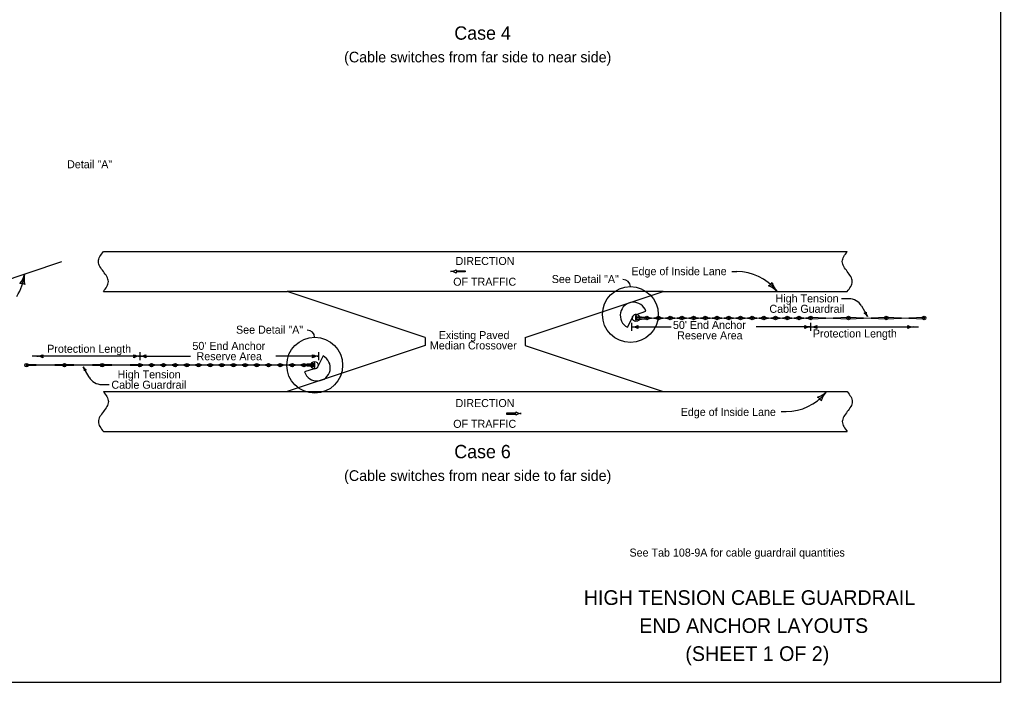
# Model space of a CAD drawing. Extents: x 10133 to 81668, y 7924 to 11018.
# Drawn here: x 11797 to 13268, y 7924 to 8918 of the extents above; entities that cross this region are included whole.
import ezdxf

# ---------------------------------------------------------------- set-up
doc = ezdxf.new("R2010")
doc.units = 0
for name, color, linetype in [('dsnCellElements', 7, 'Continuous'), ('dsnShadingGranular', 7, 'Continuous'), ('DsnShtRevisedText', 7, 'Continuous'), ('dsnStdDimension', 7, 'Continuous'), ('Level 8', 7, 'Continuous'), ('SheetBorder', 7, 'Continuous')]:
    doc.layers.add(name, color=color, linetype=linetype)

msp = doc.modelspace()

# ---------------------------------------------------------------- linework, layer by layer
at = {"layer": 'dsnCellElements'}
for p, q in [((12721, 8472.6), (12737.8, 8471.4)), ((12721, 8471.4), (12736.9, 8471.4)), ((12721, 8469.2), (12736.9, 8469.2)), ((12721, 8468), (12737.8, 8469.2)), ((12737.8, 8469.2), (12754.4, 8471.4)), ((12737.8, 8471.4), (12754.4, 8469.2)), ((12755.3, 8469.2), (12771.9, 8471.4)), ((12755.3, 8471.4), (12771.9, 8469.2)), ((12772.9, 8469.2), (12789.5, 8471.4)), ((12772.9, 8471.4), (12789.5, 8469.2)), ((12790.4, 8469.2), (12807, 8471.4)), ((12790.4, 8471.4), (12807, 8469.2)), ((12808, 8469.2), (12824.6, 8471.4)), ((12808, 8471.4), (12824.6, 8469.2)), ((12825.5, 8469.2), (12842.1, 8471.4)), ((12825.5, 8471.4), (12842.1, 8469.2)), ((12843.1, 8471.4), (12859.7, 8469.2)), ((12843.1, 8469.2), (12859.7, 8471.4)), ((12860.6, 8469.2), (12877.2, 8471.4)), ((12860.6, 8471.4), (12877.2, 8469.2)), ((12878.2, 8469.2), (12894.8, 8471.4)), ((12878.2, 8471.4), (12894.8, 8469.2)), ((12895.7, 8469.2), (12912.3, 8471.4)), ((12895.7, 8471.4), (12912.3, 8469.2)), ((12913.3, 8469.2), (12929.8, 8471.4)), ((12913.3, 8471.4), (12929.8, 8469.2)), ((12930.8, 8469.2), (12947.4, 8471.4)), ((12930.8, 8471.4), (12947.4, 8469.2)), ((12948.4, 8469.2), (12964.9, 8471.4)), ((12948.4, 8471.4), (12964.9, 8469.2)), ((12965.9, 8469.2), (12982.5, 8471.4)), ((12965.9, 8471.4), (12982.5, 8469.2)), ((12983.4, 8469.2), (13039.2, 8471.4)), ((12983.4, 8471.4), (13039.2, 8469.2)), ((13040.1, 8469.2), (13095.9, 8471.4)), ((13040.1, 8471.4), (13095.9, 8469.2)), ((13096.9, 8469.2), (13152.6, 8471.4)), ((13096.9, 8471.4), (13152.6, 8469.2)), ((11863.2, 8400.6), (11807.4, 8398.3)), ((11863.2, 8398.3), (11807.4, 8400.6)), ((11919.9, 8400.6), (11864.1, 8398.3)), ((11919.9, 8398.3), (11864.1, 8400.6)), ((11976.6, 8400.6), (11920.8, 8398.3)), ((11976.6, 8398.3), (11920.8, 8400.6)), ((11994.2, 8400.6), (11977.5, 8398.3)), ((11994.2, 8398.3), (11977.5, 8400.6)), ((12011.7, 8400.6), (11995.1, 8398.3)), ((12011.7, 8398.3), (11995.1, 8400.6)), ((12029.3, 8400.6), (12012.6, 8398.3)), ((12029.3, 8398.3), (12012.6, 8400.6)), ((12046.8, 8400.6), (12030.2, 8398.3)), ((12046.8, 8398.3), (12030.2, 8400.6)), ((12064.4, 8400.6), (12047.7, 8398.3)), ((12064.4, 8398.3), (12047.7, 8400.6)), ((12081.9, 8400.6), (12065.3, 8398.3)), ((12081.9, 8398.3), (12065.3, 8400.6)), ((12099.4, 8400.6), (12082.8, 8398.3)), ((12099.4, 8398.3), (12082.8, 8400.6)), ((12117, 8398.3), (12100.4, 8400.6)), ((12117, 8400.6), (12100.4, 8398.3)), ((12134.5, 8400.6), (12117.9, 8398.3)), ((12134.5, 8398.3), (12117.9, 8400.6)), ((12152.1, 8400.6), (12135.5, 8398.3)), ((12152.1, 8398.3), (12135.5, 8400.6)), ((12169.6, 8400.6), (12153, 8398.3)), ((12169.6, 8398.3), (12153, 8400.6)), ((12187.2, 8400.6), (12170.6, 8398.3)), ((12187.2, 8398.3), (12170.6, 8400.6)), ((12204.7, 8400.6), (12188.1, 8398.3)), ((12204.7, 8398.3), (12188.1, 8400.6)), ((12222.3, 8400.6), (12205.7, 8398.3)), ((12222.3, 8398.3), (12205.7, 8400.6)), ((12239, 8401.8), (12222.3, 8400.6)), ((12239, 8400.6), (12223.2, 8400.6)), ((12239, 8397.2), (12222.3, 8398.3)), ((12239, 8398.3), (12223.2, 8398.3))]:
    msp.add_line(p, q, dxfattribs=at)
for points in [[(12720.4, 8473.3), (12720.4, 8467.3), (12721.6, 8467.3), (12721.6, 8473.3)], [(12736.9, 8471.4), (12736.9, 8469.2), (12737.8, 8469.2), (12737.8, 8471.4)], [(12754.4, 8471.4), (12754.4, 8469.2), (12755.3, 8469.2), (12755.3, 8471.4)], [(12772, 8471.4), (12772, 8469.2), (12772.9, 8469.2), (12772.9, 8471.4)], [(12789.5, 8471.4), (12789.5, 8469.2), (12790.4, 8469.2), (12790.4, 8471.4)], [(12807.1, 8471.4), (12807.1, 8469.2), (12808, 8469.2), (12808, 8471.4)], [(12824.6, 8471.4), (12824.6, 8469.2), (12825.5, 8469.2), (12825.5, 8471.4)], [(12842.1, 8471.4), (12842.1, 8469.2), (12843.1, 8469.2), (12843.1, 8471.4)], [(12859.7, 8471.4), (12859.7, 8469.2), (12860.6, 8469.2), (12860.6, 8471.4)], [(12877.2, 8471.4), (12877.2, 8469.2), (12878.2, 8469.2), (12878.2, 8471.4)], [(12894.8, 8471.4), (12894.8, 8469.2), (12895.7, 8469.2), (12895.7, 8471.4)], [(12912.3, 8471.4), (12912.3, 8469.2), (12913.3, 8469.2), (12913.3, 8471.4)], [(12929.8, 8471.4), (12929.8, 8469.2), (12930.8, 8469.2), (12930.8, 8471.4)], [(12947.4, 8471.4), (12947.4, 8469.2), (12948.4, 8469.2), (12948.4, 8471.4)], [(12964.9, 8471.4), (12964.9, 8469.2), (12965.9, 8469.2), (12965.9, 8471.4)], [(12982.5, 8471.4), (12982.5, 8469.2), (12983.4, 8469.2), (12983.4, 8471.4)], [(12982.5, 8471.4), (12982.5, 8469.2), (12983.4, 8469.2), (12983.4, 8471.4)], [(13039.2, 8471.4), (13039.2, 8469.2), (13040.1, 8469.2), (13040.1, 8471.4)], [(13039.2, 8471.4), (13039.2, 8469.2), (13040.1, 8469.2), (13040.1, 8471.4)], [(13095.9, 8471.4), (13095.9, 8469.2), (13096.9, 8469.2), (13096.9, 8471.4)], [(13095.9, 8471.4), (13095.9, 8469.2), (13096.9, 8469.2), (13096.9, 8471.4)], [(13152.6, 8471.4), (13152.6, 8469.2), (13153.6, 8469.2), (13153.6, 8471.4)], [(11807.4, 8398.3), (11807.4, 8400.6), (11806.5, 8400.6), (11806.5, 8398.3)], [(11864.1, 8398.3), (11864.1, 8400.6), (11863.2, 8400.6), (11863.2, 8398.3)], [(11864.1, 8398.3), (11864.1, 8400.6), (11863.2, 8400.6), (11863.2, 8398.3)], [(11920.8, 8398.3), (11920.8, 8400.6), (11919.9, 8400.6), (11919.9, 8398.3)], [(11920.8, 8398.3), (11920.8, 8400.6), (11919.9, 8400.6), (11919.9, 8398.3)], [(11977.5, 8398.3), (11977.5, 8400.6), (11976.6, 8400.6), (11976.6, 8398.3)], [(11977.5, 8398.3), (11977.5, 8400.6), (11976.6, 8400.6), (11976.6, 8398.3)], [(11995.1, 8398.3), (11995.1, 8400.6), (11994.2, 8400.6), (11994.2, 8398.3)], [(12012.6, 8398.3), (12012.6, 8400.6), (12011.7, 8400.6), (12011.7, 8398.3)], [(12030.2, 8398.3), (12030.2, 8400.6), (12029.3, 8400.6), (12029.3, 8398.3)], [(12047.7, 8398.3), (12047.7, 8400.6), (12046.8, 8400.6), (12046.8, 8398.3)], [(12065.3, 8398.3), (12065.3, 8400.6), (12064.4, 8400.6), (12064.4, 8398.3)], [(12082.8, 8398.3), (12082.8, 8400.6), (12081.9, 8400.6), (12081.9, 8398.3)], [(12100.4, 8398.3), (12100.4, 8400.6), (12099.4, 8400.6), (12099.4, 8398.3)], [(12117.9, 8398.3), (12117.9, 8400.6), (12117, 8400.6), (12117, 8398.3)], [(12135.5, 8398.3), (12135.5, 8400.6), (12134.5, 8400.6), (12134.5, 8398.3)], [(12153, 8398.3), (12153, 8400.6), (12152.1, 8400.6), (12152.1, 8398.3)], [(12170.6, 8398.3), (12170.6, 8400.6), (12169.6, 8400.6), (12169.6, 8398.3)], [(12188.1, 8398.3), (12188.1, 8400.6), (12187.2, 8400.6), (12187.2, 8398.3)], [(12205.7, 8398.3), (12205.7, 8400.6), (12204.7, 8400.6), (12204.7, 8398.3)], [(12223.2, 8398.3), (12223.2, 8400.6), (12222.3, 8400.6), (12222.3, 8398.3)], [(12239.6, 8396.5), (12239.6, 8402.5), (12238.4, 8402.5), (12238.4, 8396.5)]]:
    msp.add_lwpolyline(points, close=True, dxfattribs=at)
for centre, radius in [((12721, 8470.3), 5.4), ((12737.3, 8470.3), 2.66), ((12754.8, 8470.3), 2.66), ((12772.4, 8470.3), 2.66), ((12789.9, 8470.3), 2.66), ((12807.5, 8470.3), 2.66), ((12825, 8470.3), 2.66), ((12842.6, 8470.3), 2.66), ((12860.1, 8470.3), 2.66), ((12877.7, 8470.3), 2.66), ((12895.2, 8470.3), 2.66), ((12912.8, 8470.3), 2.66), ((12930.3, 8470.3), 2.66), ((12947.9, 8470.3), 2.66), ((12965.4, 8470.3), 2.66), ((12983, 8470.3), 2.66), ((12983, 8470.3), 2.66), ((13039.7, 8470.3), 2.66), ((13039.7, 8470.3), 2.66), ((13096.4, 8470.3), 2.66), ((13096.4, 8470.3), 2.66), ((13153.1, 8470.3), 2.66), ((11807, 8399.5), 2.66), ((11863.7, 8399.5), 2.66), ((11863.7, 8399.5), 2.66), ((11920.4, 8399.5), 2.66), ((11920.4, 8399.5), 2.66), ((11977.1, 8399.5), 2.66), ((11977.1, 8399.5), 2.66), ((11994.6, 8399.5), 2.66), ((12012.2, 8399.5), 2.66), ((12029.7, 8399.5), 2.66), ((12047.3, 8399.5), 2.66), ((12064.8, 8399.5), 2.66), ((12082.3, 8399.5), 2.66), ((12099.9, 8399.5), 2.66), ((12117.4, 8399.5), 2.66), ((12135, 8399.5), 2.66), ((12152.5, 8399.5), 2.66), ((12170.1, 8399.5), 2.66), ((12187.6, 8399.5), 2.66), ((12205.2, 8399.5), 2.66), ((12222.7, 8399.5), 2.66), ((12239, 8399.5), 5.4)]:
    msp.add_circle(centre, radius, dxfattribs=at)
at = {"layer": 'DsnShtRevisedText'}
for p, q in [((11602.1, 8468.7), (11860.1, 8554.7)), ((12443, 8540.1), (12443, 8540.1)), ((12451.1, 8542.6), (12451.1, 8540.8)), ((12451.1, 8540.8), (12465, 8540.8)), ((12465, 8539.3), (12451.1, 8539.3)), ((12451.1, 8539.3), (12451.1, 8537.5)), ((12465, 8540.8), (12465, 8539.3)), ((12864.7, 8539.7), (12872.2, 8539.7)), ((13040.3, 8499.1), (13029.1, 8499.1)), ((13059.1, 8488.3), (13068, 8472.7)), ((12721.8, 8475.7), (12736, 8480.4)), ((12721.8, 8475.7), (12736, 8480.4)), ((12708.4, 8456.5), (12715.7, 8471.1)), ((12708.4, 8456.5), (12715.7, 8471.1)), ((12715, 8450.8), (12715, 8462.8)), ((12983.1, 8450.8), (12983.1, 8462.8)), ((12715, 8456.8), (12773.9, 8456.8)), ((12983.1, 8456.8), (12901.2, 8456.8)), ((12983.1, 8456.8), (13092.6, 8456.8)), ((13092.6, 8456.8), (13144.9, 8456.8)), ((11977, 8419), (11977, 8407)), ((12245.1, 8419), (12245.1, 8407)), ((11942.5, 8413), (11815.2, 8413)), ((11977, 8413), (11942.5, 8413)), ((11977, 8413), (12052.7, 8413)), ((12245.1, 8413), (12181.1, 8413)), ((12251.7, 8413.3), (12244.4, 8398.7)), ((12251.7, 8413.3), (12244.4, 8398.7)), ((11900.9, 8381.5), (11892.1, 8397.1)), ((12238.3, 8394.1), (12224.1, 8389.4)), ((12238.3, 8394.1), (12224.1, 8389.4)), ((11919.7, 8370.6), (11931, 8370.6)), ((12540.9, 8327.8), (12526.9, 8327.8)), ((12526.9, 8327.8), (12526.9, 8326.3)), ((12526.9, 8326.3), (12540.9, 8326.3)), ((12540.9, 8329.6), (12540.9, 8327.8)), ((12540.9, 8326.3), (12540.9, 8324.5)), ((12549, 8327.1), (12549, 8327.1)), ((12938.6, 8330), (12946.1, 8330))]:
    msp.add_line(p, q, dxfattribs=at)
for centre in [(12712.6, 8475.4), (12239.2, 8399.5)]:
    msp.add_circle(centre, 41.9, dxfattribs=at)
for centre, radius, start, end in [((11724.4, 8544.9), 80.1, 328.1378, 353.6325), ((11772.5, 8543.3), 32.4, 318.907, 346.9794), ((11835.6, 8528.7), 32.4, 166.9794, 195.0519), ((12442.3, 8556.4), 16.4, 272.352, 302.382), ((12442.3, 8523.7), 16.4, 57.618, 87.648), ((12872.2, 8463.6), 76.2, 39.0106, 90), ((11797.9, 8509.6), 12.5, 59.2461, 94.7128), ((12701.8, 8517), 10.8, 1.4994, 91.4994), ((12914.2, 8529.7), 12.5, 295.2639, 330.7306), ((12909, 8487.8), 32.4, 42.9973, 71.0698), ((12956.4, 8532), 32.4, 194.9248, 222.9973), ((12717.2, 8474.1), 19.8, 18.4349, 243.4349), ((12717.2, 8474.1), 19.8, 18.4349, 243.4349), ((13040.3, 8477.3), 21.8, 30.2243, 90), ((12721.1, 8470.3), 5.4, 81.8699, 171.8699), ((12721.1, 8470.3), 5.4, 81.8699, 171.8699), ((13062.3, 8482.5), 5.25, 282.498, 317.9647), ((13056.2, 8465.8), 13.6, 30.2314, 58.3038), ((13079.8, 8479.5), 13.6, 182.1589, 210.2314), ((12715, 8475.9), 19.1, 270, 298.0725), ((12731, 8456.8), 7.39, 162.2666, 197.7334), ((12967, 8456.8), 7.39, 342.2666, 17.7333), ((12983.1, 8475.9), 19.1, 241.9275, 270), ((12983.1, 8475.9), 19.1, 270, 298.0725), ((12999.1, 8456.8), 7.39, 162.2666, 197.7334), ((13121.5, 8456.8), 7.39, 342.2667, 17.7334), ((13137.6, 8475.9), 19.1, 241.9275, 270), ((12228.3, 8441.1), 10.8, 1.4994, 91.4994), ((12715, 8437.7), 19.1, 61.9275, 90), ((12983.1, 8437.7), 19.1, 90, 118.0725), ((12983.1, 8437.7), 19.1, 61.9275, 90), ((13137.6, 8437.7), 19.1, 90, 118.0725), ((11822.5, 8432.1), 19.1, 270, 298.0725), ((11838.5, 8413), 7.39, 162.2666, 197.7334), ((11960.9, 8413), 7.39, 342.2666, 17.7333), ((11977, 8432.1), 19.1, 241.9275, 270), ((11977, 8432.1), 19.1, 270, 298.0725), ((11993, 8413), 7.39, 162.2666, 197.7334), ((12229, 8413), 7.39, 342.2667, 17.7334), ((12245.1, 8432.1), 19.1, 241.9275, 270), ((11822.5, 8393.9), 19.1, 61.9275, 90), ((11977, 8393.9), 19.1, 90, 118.0725), ((11977, 8393.9), 19.1, 61.9275, 90), ((12242.8, 8395.6), 19.8, 198.4349, 63.4349), ((12242.8, 8395.6), 19.8, 198.4349, 63.4349), ((12245.1, 8393.9), 19.1, 90, 118.0725), ((11880.3, 8390.3), 13.6, 2.1589, 30.2314), ((11903.8, 8404), 13.6, 210.2314, 238.3038), ((11897.8, 8387.3), 5.25, 102.498, 137.9647), ((12239, 8399.5), 5.4, 261.8699, 351.8699), ((12239, 8399.5), 5.4, 261.8699, 351.8699), ((11919.7, 8392.4), 21.8, 210.2243, 270), ((12946.1, 8406.2), 76.2, 270, 320.9894), ((12982.9, 8382), 32.4, 288.9302, 317.0027), ((13030.3, 8337.8), 32.4, 137.0027, 165.0752), ((12988.1, 8340), 12.5, 29.2694, 64.7361), ((12549.7, 8343.4), 16.4, 237.618, 267.648), ((12549.7, 8310.7), 16.4, 92.352, 122.382)]:
    msp.add_arc(centre, radius, start, end, dxfattribs=at)
at = {"layer": 'dsnStdDimension'}
for p, q in [((11922.2, 8569.9), (13037.9, 8569.9)), ((11922.2, 8509.9), (12198, 8509.9)), ((12405, 8440.9), (12198, 8509.9)), ((12762, 8509.9), (12198, 8509.9)), ((12555, 8440.9), (12762, 8509.9)), ((12758.9, 8509.9), (13037.9, 8509.9)), ((12405, 8428.9), (12198, 8359.9)), ((12405, 8440.9), (12405, 8428.9)), ((12555, 8440.9), (12555, 8428.9)), ((12555, 8428.9), (12762, 8359.9)), ((11922.2, 8359.9), (12201.1, 8359.9)), ((12201.1, 8359.9), (12762, 8359.9)), ((12762, 8359.9), (13037.9, 8359.9)), ((11922.2, 8299.9), (13037.9, 8299.9))]:
    msp.add_line(p, q, dxfattribs=at)
for points in [[(11922.2, 8509.9), (11929.7, 8524.9), (11922.2, 8539.9), (11914.7, 8554.9), (11922.2, 8569.9)], [(13037.9, 8509.9), (13045.4, 8524.9), (13037.9, 8539.9), (13030.4, 8554.9), (13037.9, 8569.9)], [(11922.2, 8359.9), (11929.7, 8344.9), (11922.2, 8329.9), (11914.7, 8314.9), (11922.2, 8299.9)], [(13037.9, 8359.9), (13045.4, 8344.9), (13037.9, 8329.9), (13030.4, 8314.9), (13037.9, 8299.9)]]:
    msp.add_spline(points, degree=3, dxfattribs=at)
at = {"layer": 'SheetBorder'}
msp.add_lwpolyline([(10132.5, 9944), (13267.5, 9944), (13267.5, 7924), (10132.5, 7924)], close=True, dxfattribs=at)

# ---------------------------------------------------------------- texts
at = {"layer": 'dsnShadingGranular'}
for s, p in [('HIGH TENSION CABLE GUARDRAIL', (12642.8, 8040.1)), ('END ANCHOR LAYOUTS', (12725.9, 7998.1)), ('(SHEET 1 OF 2)', (12795.1, 7956.1))]:
    msp.add_text(s, height=22, dxfattribs=at).set_placement(p)
at = {"layer": 'DsnShtRevisedText'}
for s, p in [('Detail "A"', (11867.8, 8694.7)), ('DIRECTION', (12450.5, 8549.7)), ('Edge of Inside Lane', (12714.2, 8534.4)), ('See Detail "A"', (12594.7, 8522.6)), ('OF TRAFFIC', (12446.9, 8518.6)), ('High Tension', (12930.4, 8493.6)), ('Cable Guardrail', (12921.1, 8478)), ('See Detail "A"', (12121.2, 8446.7)), ("50' End Anchor", (12776.5, 8453.8)), ('Existing Paved', (12425.2, 8438.6)), ('Reserve Area', (12782.8, 8438.2)), ('Protection Length', (12986.4, 8441)), ('Protection Length', (11838, 8418.1)), ("50' End Anchor", (12055.8, 8422.4)), ('Median Crossover', (12411.9, 8423.1)), ('Reserve Area', (12062, 8406.9)), ('High Tension', (11943.6, 8379.7)), ('Cable Guardrail', (11934.3, 8364.2)), ('DIRECTION', (12450.5, 8336.7)), ('Edge of Inside Lane', (12788.1, 8323.4)), ('OF TRAFFIC', (12446.9, 8305.6))]:
    msp.add_text(s, height=12, dxfattribs=at).set_placement(p)
at = {"layer": 'Level 8'}
for s, height, p in [('Case 4', 20, (12448.6, 8887.4)), ('(Cable switches from far side to near side)', 16, (12283.3, 8853.4)), ('Case 6', 20, (12448.5, 8260)), ('(Cable switches from near side to far side)', 16, (12283.3, 8226)), ('See Tab 108-9A for cable guardrail quantities', 12, (12711.3, 8112.6))]:
    msp.add_text(s, height=height, dxfattribs=at).set_placement(p)

doc.saveas('drawing.dxf')
